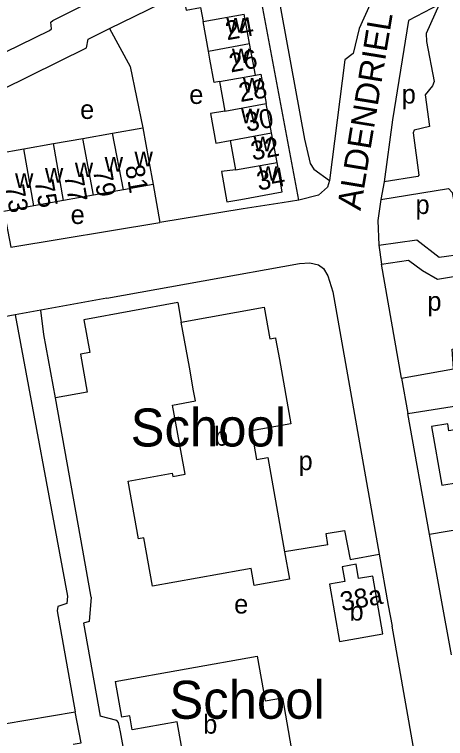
# Model space of a CAD drawing. Extents: x 157794 to 159375, y 380877 to 382306.
# Drawn here: x 158697 to 158787.7, y 381550.6 to 381703 of the extents above; entities that cross this region are included whole.
import ezdxf

# ---------------------------------------------------------------- set-up
doc = ezdxf.new("R2010")
doc.units = 0
for name, color, linetype in [('BLT_Basislijn', 7, 'Continuous'), ('BLT_Bebouwing', 7, 'Continuous'), ('BLT_Bebouwing_beschrifting', 7, 'Continuous'), ('BLT_Centroide', 7, 'Continuous'), ('BLT_Huisnummer', 7, 'Continuous'), ('BLT_Huisnummer_ tussenligend', 7, 'Continuous'), ('BLT_Onderverdeling_panden', 7, 'Continuous'), ('BLT_Straatnaam', 7, 'Continuous')]:
    doc.layers.add(name, color=color, linetype=linetype)

msp = doc.modelspace()

# ---------------------------------------------------------------- linework, layer by layer
at = {"layer": 'BLT_Basislijn'}
for p, q in [((158716.99, 381700.06), (158732.42, 381707.65)), ((158726.17, 381667.25), (158727.57, 381659.23)), ((158774.74, 381667.82), (158774.08, 381664.1)), ((158773.68, 381654.43), (158774.2, 381650.42)), ((158778.42, 381626.43), (158774.2, 381650.42)), ((158716.44, 381643.28), (158702.55, 381640.77)), ((158731.34, 381642.41), (158732.08, 381638.26)), ((158697.15, 381639.79), (158665.27, 381634.06)), ((158702.55, 381640.77), (158697.15, 381639.79)), ((158778.42, 381626.43), (158779.74, 381619.03)), ((158711.34, 381590.25), (158705.6, 381622.3)), ((158784.32, 381593.58), (158779.74, 381619.03)), ((158784.32, 381593.58), (158833.83, 381602.23)), ((158762.95, 381591.37), (158762.56, 381593.77)), ((158788.97, 381568.19), (158784.32, 381593.58)), ((158762.95, 381591.37), (158753.82, 381589.89)), ((158713.13, 381580.33), (158711.34, 381590.25)), ((158775.63, 381578.58), (158776.43, 381574.23)), ((158694.77, 381553.68), (158709.75, 381556.17))]:
    msp.add_line(p, q, dxfattribs=at)
for points in [[(158782.36, 381724.73), (158774.85, 381721.25), (158752.36, 381709.92), (158752.12, 381709.08), (158757.99, 381676.79), (158759.2, 381671.63), (158759.99, 381670.45), (158763.24, 381668.05)], [(158782.36, 381724.73), (158784.91, 381719.82), (158785.13, 381718.93), (158784.65, 381716.54), (158784.18, 381715.81), (158775.58, 381709.73), (158771.84, 381705.21), (158769.52, 381700.05), (158768.24, 381694.81), (158766.51, 381693.47), (158763.24, 381668.05)], [(158676.42, 381708.23), (158685.06, 381690.53), (158685.76, 381690.61), (158704.31, 381699.68), (158704.78, 381699.99), (158704.62, 381701.43), (158705.04, 381701.74), (158730.07, 381714.32)], [(158756.8, 381663.95), (158747.99, 381711.13), (158743.71, 381712.16), (158742.71, 381712.87)], [(158786.33, 381705.11), (158779.92, 381701.77), (158776.5, 381680.83), (158774.74, 381667.82)], [(158786.33, 381705.11), (158783.62, 381699.01), (158783.7, 381697.35), (158785.32, 381688.89), (158784.97, 381687.97), (158783.38, 381686.09), (158784.33, 381679.41), (158781.07, 381678.63), (158780.85, 381678.09), (158782.09, 381669.18), (158781.86, 381668.93), (158774.74, 381667.82)], [(158692.52, 381673.59), (158692.06, 381675.65), (158688.35, 381684.3), (158712.13, 381695.99), (158712.48, 381697.86), (158716.99, 381700.06)], [(158716.99, 381700.06), (158721.33, 381692.04), (158724.01, 381679.19)], [(158763.24, 381668.05), (158762.86, 381666.68), (158760.98, 381664.98), (158756.8, 381663.95)], [(158774.08, 381664.1), (158788.28, 381666.37), (158789.08, 381665.52), (158791.47, 381652.64)], [(158774.08, 381664.1), (158773.41, 381659.65), (158773.68, 381654.43)], [(158756.8, 381663.95), (158753.34, 381663.36), (158745.12, 381662.1), (158727.57, 381659.23)], [(158694.92, 381660.63), (158696.24, 381654.04), (158727.57, 381659.23)], [(158773.68, 381654.43), (158781.63, 381655.58), (158786.32, 381651.95), (158791.47, 381652.64)], [(158716.44, 381643.28), (158756.97, 381650.6), (158759.12, 381650.7), (158760.95, 381650.29), (158762, 381649.56), (158762.93, 381647.99), (158763.97, 381644.63), (158773.73, 381589.37)], [(158774.2, 381650.42), (158779.88, 381651.31), (158782.81, 381649.09), (158786.02, 381647.3), (158796.48, 381649.08)], [(158779.74, 381619.03), (158793.09, 381621.12), (158806.61, 381623.6), (158807.09, 381623.95), (158810.36, 381629.1), (158809.24, 381636.67), (158806.56, 381650.74)], [(158778.42, 381626.43), (158789.37, 381628.4), (158789.08, 381632.56), (158795.95, 381633.89), (158796.02, 381634.82), (158794.77, 381641.99), (158797.46, 381642.72), (158797.3, 381644.99), (158796.48, 381649.08)], [(158731.34, 381642.41), (158711.59, 381638.7), (158712.86, 381631.83), (158710.89, 381631.47), (158712.3, 381623.51), (158705.6, 381622.3)], [(158697.15, 381639.79), (158708.12, 381580.51), (158708, 381579), (158706.07, 381578.4), (158705.99, 381577.49), (158709.75, 381556.17)], [(158705.6, 381622.3), (158703.16, 381635.61), (158702.55, 381640.77)], [(158762.56, 381593.77), (158766.42, 381594.4)], [(158766.42, 381594.4), (158767.65, 381588.27), (158773.73, 381589.37)], [(158773.73, 381589.37), (158775.63, 381578.58)], [(158713.13, 381580.33), (158712.7, 381575.24), (158711.53, 381574.87), (158714.98, 381555.3)], [(158786.85, 381515.06), (158786.62, 381516.36), (158776.43, 381574.23)], [(158709.29, 381549.36), (158710.98, 381549.66), (158709.75, 381556.17)], [(158731.74, 381486.25), (158728.66, 381500), (158719.31, 381551.96), (158718.87, 381553.92), (158718.53, 381554.37), (158714.98, 381555.3)]]:
    msp.add_lwpolyline(points, dxfattribs=at)
at = {"layer": 'BLT_Bebouwing'}
for p, q in [((158746.46, 381696.9), (158745.34, 381703.11)), ((158737.79, 381695.32), (158736.66, 381701.53)), ((158747.67, 381690.25), (158746.46, 381696.9)), ((158740.14, 381688.88), (158741.26, 381682.69)), ((158751.09, 381678.08), (158749.97, 381684.27)), ((158711.39, 381676.94), (158717.61, 381678.04)), ((158717.61, 381678.04), (158724.01, 381679.19)), ((158752.22, 381671.88), (158751.09, 381678.08)), ((158705.17, 381675.84), (158711.39, 381676.94)), ((158742.39, 381676.49), (158743.51, 381670.3)), ((158692.52, 381673.59), (158698.94, 381674.74)), ((158698.94, 381674.74), (158705.17, 381675.84)), ((158726.17, 381667.25), (158719.89, 381666.11)), ((158719.89, 381666.11), (158713.6, 381664.98)), ((158713.6, 381664.98), (158707.31, 381663.84)), ((158701.02, 381662.7), (158694.74, 381661.56)), ((158707.31, 381663.84), (158701.02, 381662.7)), ((158718.13, 381562.6), (158719.47, 381555.05))]:
    msp.add_line(p, q, dxfattribs=at)
for points in [[(158732.42, 381707.65), (158733.1, 381703.91), (158736.13, 381704.46), (158736.66, 381701.53)], [(158740.14, 381688.88), (158739, 381688.68), (158738.1, 381693.6), (158737.79, 381695.32)], [(158747.67, 381690.25), (158748.84, 381690.47), (158749.97, 381684.27)], [(158741.26, 381682.69), (158738.25, 381682.14), (158739.38, 381675.95), (158742.39, 381676.49)], [(158724.01, 381679.19), (158725.28, 381672.17), (158726.17, 381667.25)], [(158743.51, 381670.3), (158740.52, 381669.94), (158741.68, 381663.56), (158744.64, 381664.1), (158753.34, 381665.68), (158752.22, 381671.88)], [(158732.08, 381638.26), (158749.55, 381641.38), (158750.73, 381634.74), (158751.87, 381634.94), (158751.9, 381634.83), (158752.72, 381630.35)], [(158731.09, 381616.19), (158730.26, 381620.79), (158735.05, 381621.65), (158734.67, 381623.78), (158733.79, 381628.73), (158732.08, 381638.26)], [(158752.72, 381630.35), (158755.13, 381616.85), (158746.85, 381615.37), (158747.93, 381609.3), (158750.28, 381609.72), (158753.4, 381592.26)], [(158794.67, 381616.47), (158788.4, 381615.37), (158788.14, 381616.84), (158784.76, 381616.25), (158786.93, 381603.89), (158790.34, 381604.49), (158789.96, 381606.59), (158796.21, 381607.69)], [(158723.04, 381592.65), (158720.87, 381604.77), (158730.17, 381606.43), (158730.29, 381605.74), (158732.87, 381606.2), (158731.09, 381616.19)], [(158753.82, 381589.89), (158754.85, 381584.12), (158747.43, 381582.79), (158746.79, 381586.34), (158744.82, 381585.99), (158726.02, 381582.63), (158724.19, 381592.86), (158723.04, 381592.65)], [(158753.4, 381592.26), (158753.82, 381589.89)], [(158718.13, 381562.6), (158748.07, 381567.91)], [(158748.07, 381567.91), (158749.74, 381558.48), (158753.36, 381559.12), (158755.22, 381548.64), (158750.43, 381547.79)], [(158732.03, 381515.6), (158729.38, 381530.51), (158733.71, 381531.28), (158732.57, 381537.7), (158734.06, 381537.97), (158731.19, 381554.1), (158721.76, 381552.43), (158721.24, 381555.36), (158719.47, 381555.05)]]:
    msp.add_lwpolyline(points, dxfattribs=at)
msp.add_lwpolyline([(158768.85, 381587.28), (158765.92, 381586.74), (158766.47, 381583.65), (158763.28, 381583.08), (158765.37, 381571), (158774.5, 381572.58), (158772.37, 381584.74), (158769.39, 381584.23)], close=True, dxfattribs=at)
at = {"layer": 'BLT_Onderverdeling_panden'}
for p, q in [((158736.66, 381701.53), (158745.34, 381703.11)), ((158737.79, 381695.32), (158746.46, 381696.9)), ((158740.14, 381688.88), (158747.67, 381690.25)), ((158741.26, 381682.69), (158749.97, 381684.27)), ((158719.89, 381666.11), (158717.61, 381678.04)), ((158742.39, 381676.49), (158751.09, 381678.08)), ((158713.6, 381664.98), (158711.39, 381676.94)), ((158701.02, 381662.7), (158698.94, 381674.74)), ((158707.31, 381663.84), (158705.17, 381675.84)), ((158743.51, 381670.3), (158752.22, 381671.88))]:
    msp.add_line(p, q, dxfattribs=at)

# ---------------------------------------------------------------- texts
at = {"layer": 'BLT_Bebouwing_beschrifting'}
for p in [(158721.41, 381612.06), (158729.56, 381554.73)]:
    msp.add_text('School', height=8, dxfattribs=at).set_placement(p)
at = {"layer": 'BLT_Centroide'}
for s, p in [('w', (158741.56, 381699.22)), ('w', (158742.73, 381692.78)), ('w', (158745.05, 381686.56)), ('e', (158733.76, 381684.19)), ('p', (158778.46, 381684.27)), ('e', (158710.79, 381681.03)), ('w', (158744.67, 381680.09)), ('w', (158747.3, 381674.19)), ('w', (158722.23, 381671.05)), ('w', (158709.67, 381668.77)), ('w', (158715.95, 381669.92)), ('w', (158703.38, 381667.64)), ('w', (158748.43, 381668)), ('w', (158697.09, 381666.5)), ('p', (158781.37, 381661.01)), ('e', (158708.79, 381658.91)), ('p', (158783.86, 381640.65)), ('b', (158738.97, 381612.22)), ('p', (158756.76, 381607.07)), ('e', (158743.2, 381576.89)), ('b', (158767.48, 381575.41)), ('b', (158736.69, 381551.59))]:
    msp.add_text(s, height=4, dxfattribs=at).set_placement(p)
at = {"layer": 'BLT_Huisnummer'}
for s, rotation, p in [('26', 10.2955, (158742.5, 381690.8)), ('30', 10.2955, (158745.89, 381678.33)), ('81', 279.9257, (158720.24, 381671.03)), ('34', 10.2955, (158748.32, 381665.93)), ('77', 279.9257, (158707.42, 381669.09)), ('73', 279.9257, (158694.99, 381666.86)), ('38a', 10.4748, (158765.91, 381577.37))]:
    msp.add_text(s, height=4, rotation=rotation, dxfattribs=at).set_placement(p)
at = {"layer": 'BLT_Huisnummer_ tussenligend'}
for s, rotation, p in [('24', 10.2955, (158741.71, 381697.58)), ('28', 10.2955, (158744.53, 381684.57)), ('32', 10.2955, (158747.08, 381672.27)), ('79', 279.9257, (158713.47, 381670.21)), ('75', 279.9257, (158701.18, 381667.93))]:
    msp.add_text(s, height=4, rotation=rotation, dxfattribs=at).set_placement(p)
at = {"layer": 'BLT_Straatnaam'}
msp.add_text('ALDENDRIEL', height=5, rotation=80.6939, dxfattribs=at).set_placement((158769.79, 381661.61))

doc.saveas('drawing.dxf')
